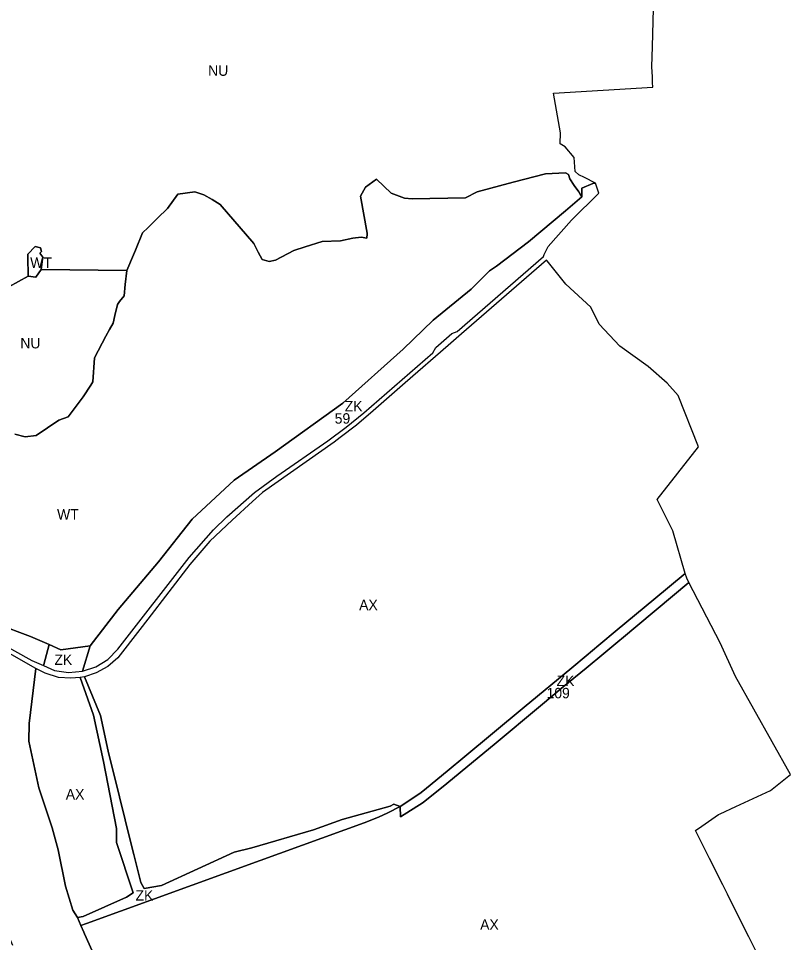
# Model space of a CAD drawing. Extents: x -521939 to -516426, y -1197857 to -1189551.
# Drawn here: x -518730 to -517990, y -1194658 to -1193772 of the extents above; entities that cross this region are included whole.
import ezdxf

# ---------------------------------------------------------------- set-up
doc = ezdxf.new("R2010")
doc.units = 0
for name, color, linetype in [('90640013', 7, 'Continuous'), ('90710013', 7, 'Continuous'), ('90710023', 7, 'Continuous'), ('90730013', 7, 'Continuous'), ('90760013', 7, 'Continuous'), ('ID_navrh', 7, 'Continuous')]:
    doc.layers.add(name, color=color, linetype=linetype)

msp = doc.modelspace()

# ---------------------------------------------------------------- linework, layer by layer
at = {"layer": '90640013'}
for points in [[(-518750.93, -1194352.24), (-518718.32, -1194364.43), (-518700.28, -1194372.27), (-518689.13, -1194377.12), (-518661.16, -1194373.51), (-518634.33, -1194338.71), (-518595.65, -1194293.01), (-518563.39, -1194252.1), (-518523.23, -1194214.71), (-518483.93, -1194187.46), (-518419.1, -1194140.67), (-518361.02, -1194088.99), (-518332.33, -1194061.21), (-518296.03, -1194031.57), (-518278.37, -1194013.9), (-518271.56, -1194009.45), (-518240.91, -1193986.11), (-518205.7, -1193956.46), (-518190.04, -1193942.98), (-518191.69, -1193940.25), (-518192.93, -1193938.18), (-518197.14, -1193931.95), (-518201.35, -1193925.72), (-518202.84, -1193921.41), (-518205.6, -1193919.97), (-518224.66, -1193920.83), (-518255.82, -1193928.83), (-518290.16, -1193938.05), (-518301.52, -1193943.97), (-518352.63, -1193944.77), (-518359.82, -1193944.27), (-518372.52, -1193939.49), (-518386.71, -1193925.92), (-518397.26, -1193933.79), (-518401.9, -1193942.24), (-518395.57, -1193977.74), (-518395.64, -1193978.34), (-518396.13, -1193982.66), (-518401.32, -1193981.65), (-518409.46, -1193982.4), (-518421.1, -1193985.13), (-518438.69, -1193985.6), (-518455.12, -1193990.99), (-518466.03, -1193994.3), (-518483.62, -1194003.52), (-518489.44, -1194004.93), (-518496.18, -1194003.01), (-518500.2, -1193996.02), (-518504.34, -1193987.83), (-518536.66, -1193950.17), (-518544.27, -1193945.64), (-518552.23, -1193940.9), (-518560.68, -1193938.11), (-518577.09, -1193940.5), (-518587.08, -1193954.16), (-518596.65, -1193963.46), (-518605.69, -1193972.18), (-518611, -1193977.3), (-518617.75, -1193994.01), (-518619.58, -1193998.55), (-518626.11, -1194013.41), (-518627.47, -1194026.91), (-518628.55, -1194037.69), (-518632.9, -1194043.41), (-518634.21, -1194045.19), (-518635, -1194046.24), (-518637.41, -1194056.78), (-518639.09, -1194064.19), (-518642.49, -1194070.13), (-518646.11, -1194076.43), (-518656.89, -1194097.14), (-518658.49, -1194120.34), (-518660.54, -1194123.45), (-518667.9, -1194134.61), (-518682.1, -1194153.73), (-518691.29, -1194156.96), (-518712.89, -1194171.66), (-518723.34, -1194172.97), (-518733.26, -1194170.62)], [(-518708.15, -1194012.57), (-518706.7, -1194002.7), (-518706.4, -1194000.63), (-518709.38, -1193996.94), (-518707.63, -1193995.36), (-518708.68, -1193991.67), (-518713.94, -1193990.62), (-518720.96, -1193997.82), (-518720.92, -1194000.53), (-518720.61, -1194019.07), (-518713.13, -1194019.83), (-518708.15, -1194012.57)]]:
    msp.add_lwpolyline(points, dxfattribs=at)
at = {"layer": '90710013'}
for points in [[(-518705.84, -1194392.3), (-518695.28, -1194396.89), (-518681.94, -1194398.95), (-518668.49, -1194397.81), (-518661.16, -1194373.51), (-518689.13, -1194377.12), (-518700.28, -1194372.27), (-518702.83, -1194381.83), (-518705.38, -1194391.38), (-518705.84, -1194392.3)], [(-518670.02, -1194641.47), (-518664.63, -1194639.51), (-518498.27, -1194579.14), (-518398.68, -1194543), (-518384.67, -1194537.56), (-518375.95, -1194533.52), (-518364.14, -1194527.29), (-518370.07, -1194525.28), (-518373.59, -1194527.14), (-518419.54, -1194539.87), (-518447.07, -1194549.8), (-518506.27, -1194566.99), (-518523.18, -1194571.3), (-518592.86, -1194603.17), (-518609.4, -1194606.14), (-518612.69, -1194600.31), (-518619.36, -1194573.41), (-518622.14, -1194562.23), (-518632.98, -1194518.19), (-518643.9, -1194474.45), (-518651.07, -1194440.25), (-518666.66, -1194403.24), (-518670.64, -1194403.6), (-518658.07, -1194439.91), (-518648.33, -1194484.39), (-518635.96, -1194548.55), (-518635.85, -1194562), (-518619.89, -1194610.13), (-518626.4, -1194614.29), (-518667.97, -1194632.81), (-518673.12, -1194633.99), (-518670.02, -1194641.47)]]:
    msp.add_lwpolyline(points, dxfattribs=at)
at = {"layer": '90710023'}
for points in [[(-518226.78, -1194000.03), (-518225.95, -1193998.27), (-518222.25, -1193990.41), (-518200, -1193965.24), (-518173.64, -1193939.33), (-518176.81, -1193929.72), (-518179.54, -1193930.3), (-518189.98, -1193934.67), (-518190.04, -1193942.98), (-518205.7, -1193956.46), (-518240.91, -1193986.11), (-518271.56, -1194009.45), (-518278.37, -1194013.9), (-518296.03, -1194031.57), (-518332.33, -1194061.21), (-518361.02, -1194088.99), (-518419.1, -1194140.67), (-518483.93, -1194187.46), (-518523.23, -1194214.71), (-518563.39, -1194252.1), (-518595.65, -1194293.01), (-518634.33, -1194338.71), (-518661.16, -1194373.51), (-518668.49, -1194397.81), (-518655.68, -1194393.54), (-518644.23, -1194386.38), (-518634.76, -1194376.7), (-518566.27, -1194288.86), (-518542.85, -1194262.27), (-518530.28, -1194249.78), (-518503.56, -1194226.5), (-518482.17, -1194210.72), (-518433.41, -1194176.9), (-518415.71, -1194163.89), (-518398.75, -1194149.91), (-518332.7, -1194092.34), (-518329.88, -1194087.32), (-518314.52, -1194073.94), (-518309.55, -1194072.16), (-518226.78, -1194000.03)], [(-518087.28, -1194312.72), (-518089.43, -1194308.57), (-518090.78, -1194303.93), (-518120.84, -1194329.01), (-518156.04, -1194358.17), (-518173.76, -1194372.91), (-518185.81, -1194382.9), (-518199.57, -1194394.33), (-518245.06, -1194432.12), (-518304.03, -1194481.14), (-518317.05, -1194491.98), (-518340.81, -1194511.5), (-518345.29, -1194514.98), (-518364.14, -1194527.29), (-518363.86, -1194537.39), (-518341.98, -1194523.73), (-518319.41, -1194505.51), (-518293.63, -1194484.18), (-518274.04, -1194467.87), (-518229.68, -1194431.04), (-518207.82, -1194412.86), (-518185.85, -1194394.67), (-518168.73, -1194380.59), (-518153.38, -1194367.87), (-518152.05, -1194366.76), (-518087.28, -1194312.72)]]:
    msp.add_lwpolyline(points, dxfattribs=at)
at = {"layer": '90730013'}
for points in [[(-518785.58, -1194054.84), (-518720.61, -1194019.07), (-518720.92, -1194000.53), (-518720.96, -1193997.82), (-518713.94, -1193990.62), (-518708.68, -1193991.67), (-518707.63, -1193995.36), (-518709.38, -1193996.94), (-518706.4, -1194000.63), (-518706.7, -1194002.7), (-518708.15, -1194012.57), (-518626.11, -1194013.41), (-518619.58, -1193998.55), (-518617.75, -1193994.01), (-518611, -1193977.3), (-518605.69, -1193972.18), (-518596.65, -1193963.46), (-518587.08, -1193954.16), (-518577.09, -1193940.5), (-518560.68, -1193938.11), (-518552.23, -1193940.9), (-518544.27, -1193945.64), (-518536.66, -1193950.17), (-518504.34, -1193987.83), (-518500.2, -1193996.02), (-518496.18, -1194003.01), (-518489.44, -1194004.93), (-518483.62, -1194003.52), (-518466.03, -1193994.3), (-518455.12, -1193990.99), (-518438.69, -1193985.6), (-518421.1, -1193985.13), (-518409.46, -1193982.4), (-518401.32, -1193981.65), (-518396.13, -1193982.66), (-518395.64, -1193978.34), (-518395.57, -1193977.74), (-518401.9, -1193942.24), (-518397.26, -1193933.79), (-518386.71, -1193925.92), (-518372.52, -1193939.49), (-518359.82, -1193944.27), (-518352.63, -1193944.77), (-518301.52, -1193943.97), (-518290.16, -1193938.05), (-518255.82, -1193928.83), (-518224.66, -1193920.83), (-518205.6, -1193919.97), (-518202.84, -1193921.41), (-518201.35, -1193925.72), (-518197.14, -1193931.95), (-518192.93, -1193938.18), (-518191.69, -1193940.25), (-518190.04, -1193942.98), (-518189.98, -1193934.67), (-518179.54, -1193930.3), (-518176.81, -1193929.72), (-518187.4, -1193924.36), (-518192.66, -1193921.7), (-518196.27, -1193918.65), (-518197.41, -1193905.18), (-518205.81, -1193894.97), (-518210.66, -1193892.12), (-518210.37, -1193881.64), (-518217.23, -1193843.45), (-518121.95, -1193837.64), (-518122.12, -1193833.28), (-518122.32, -1193828.03), (-518122.7, -1193818.24), (-518122.17, -1193798.73), (-518117.92, -1193642.32)], [(-518626.11, -1194013.41), (-518708.15, -1194012.57), (-518713.13, -1194019.83), (-518720.61, -1194019.07), (-518785.58, -1194054.84)], [(-518733.26, -1194170.62), (-518723.34, -1194172.97), (-518712.89, -1194171.66), (-518691.29, -1194156.96), (-518682.1, -1194153.73), (-518667.9, -1194134.61), (-518660.54, -1194123.45), (-518658.49, -1194120.34), (-518656.89, -1194097.14), (-518646.11, -1194076.43), (-518642.49, -1194070.13), (-518639.09, -1194064.19), (-518637.41, -1194056.78), (-518635, -1194046.24), (-518634.21, -1194045.19), (-518632.9, -1194043.41), (-518628.55, -1194037.69), (-518627.47, -1194026.91), (-518626.11, -1194013.41)], [(-518827.82, -1194325.64), (-518716.88, -1194387.49), (-518705.84, -1194392.3)], [(-518705.84, -1194392.3), (-518705.38, -1194391.38), (-518702.83, -1194381.83), (-518700.28, -1194372.27), (-518718.32, -1194364.43), (-518750.93, -1194352.24)], [(-518670.02, -1194641.47), (-518673.12, -1194633.99), (-518677.75, -1194626.77), (-518684.82, -1194603.84), (-518691.92, -1194568.93), (-518697.48, -1194547.94), (-518710.33, -1194509.64), (-518719.92, -1194464.77), (-518719.42, -1194447.81), (-518713.15, -1194395.12), (-518768.4, -1194363.91), (-518774.24, -1194362.95), (-518785.49, -1194356.68), (-518787.62, -1194357.85), (-518789.82, -1194390.1), (-518795.17, -1194469.16), (-518794.77, -1194500.94), (-518792.66, -1194516.7), (-518789.28, -1194532.25), (-518784.67, -1194547.47), (-518778.85, -1194562.27), (-518749.75, -1194628.33), (-518735.68, -1194660.28)], [(-518656.27, -1194672.17), (-518666.51, -1194649.62), (-518667.28, -1194647.83), (-518670.02, -1194641.47)]]:
    msp.add_lwpolyline(points, dxfattribs=at)
at = {"layer": '90760013'}
for points in [[(-518364.14, -1194527.29), (-518345.29, -1194514.98), (-518340.81, -1194511.5), (-518317.05, -1194491.98), (-518304.03, -1194481.14), (-518245.06, -1194432.12), (-518199.57, -1194394.33), (-518185.81, -1194382.9), (-518173.76, -1194372.91), (-518156.04, -1194358.17), (-518120.84, -1194329.01), (-518090.78, -1194303.93), (-518102.69, -1194263.13), (-518117.88, -1194232.97), (-518078.18, -1194182.6), (-518097.76, -1194133.37), (-518108.08, -1194121.7), (-518126.48, -1194105.44), (-518153.57, -1194086.04), (-518173.38, -1194065.05), (-518181.2, -1194048.7), (-518205.16, -1194026.8), (-518223.32, -1194004.32), (-518223.96, -1194003.53), (-518305.19, -1194074.33), (-518317.92, -1194085.37), (-518359.17, -1194121.38), (-518389.76, -1194148.03), (-518405.98, -1194161.92), (-518421.43, -1194173.75), (-518427.2, -1194178.07), (-518496.1, -1194226.49), (-518505.53, -1194235), (-518525.09, -1194252.86), (-518546.38, -1194272.96), (-518565.48, -1194295.54), (-518605.97, -1194347.8), (-518613.59, -1194357.67), (-518634.54, -1194384.93), (-518644.16, -1194393.22), (-518655.26, -1194399.4), (-518666.66, -1194403.24), (-518651.07, -1194440.25), (-518643.9, -1194474.45), (-518632.98, -1194518.19), (-518622.14, -1194562.23), (-518619.36, -1194573.41), (-518612.69, -1194600.31), (-518609.4, -1194606.14), (-518592.86, -1194603.17), (-518523.18, -1194571.3), (-518506.27, -1194566.99), (-518447.07, -1194549.8), (-518419.54, -1194539.87), (-518373.59, -1194527.14), (-518370.07, -1194525.28), (-518364.14, -1194527.29)], [(-518087.28, -1194312.72), (-518152.05, -1194366.76), (-518153.38, -1194367.87), (-518168.73, -1194380.59), (-518185.85, -1194394.67), (-518207.82, -1194412.86), (-518229.68, -1194431.04), (-518274.04, -1194467.87), (-518293.63, -1194484.18), (-518319.41, -1194505.51), (-518341.98, -1194523.73), (-518363.86, -1194537.39), (-518364.14, -1194527.29), (-518375.95, -1194533.52), (-518384.67, -1194537.56), (-518398.68, -1194543), (-518498.27, -1194579.14), (-518664.63, -1194639.51), (-518670.02, -1194641.47), (-518667.28, -1194647.83), (-518666.51, -1194649.62), (-518656.27, -1194672.17)], [(-518018.4, -1194675.4), (-518029.91, -1194652.44), (-518045.86, -1194620.61), (-518050.45, -1194611.46), (-518054.9, -1194602.59), (-518067.64, -1194577.17), (-518070.73, -1194570.99), (-518081.12, -1194550.28), (-518075.09, -1194546.2), (-518058.86, -1194535.22), (-518057.31, -1194534.5), (-518042.23, -1194527.44), (-518009.18, -1194511.97), (-517989.96, -1194496.69), (-518042.83, -1194402.69), (-518057.45, -1194370.47), (-518087.28, -1194312.72)], [(-518673.12, -1194633.99), (-518667.97, -1194632.81), (-518626.4, -1194614.29), (-518619.89, -1194610.13), (-518635.85, -1194562), (-518635.96, -1194548.55), (-518648.33, -1194484.39), (-518658.07, -1194439.91), (-518670.64, -1194403.6), (-518679.67, -1194404.43), (-518691.62, -1194403.86), (-518704.16, -1194399.65), (-518713.15, -1194395.12), (-518719.42, -1194447.81), (-518719.92, -1194464.77), (-518710.33, -1194509.64), (-518697.48, -1194547.94), (-518691.92, -1194568.93), (-518684.82, -1194603.84), (-518677.75, -1194626.77), (-518673.12, -1194633.99)]]:
    msp.add_lwpolyline(points, dxfattribs=at)

# ---------------------------------------------------------------- texts
at = {"layer": '90640013'}
for rotation, p in [(360, (-518718.61, -1194011.03)), (0, (-518692.84, -1194252.33))]:
    msp.add_text('WT', height=10, rotation=rotation, dxfattribs=at).set_placement(p)
at = {"layer": '90710013'}
for rotation, p in [(0, (-518695.39, -1194391.72)), (360, (-518617.65, -1194617.67))]:
    msp.add_text('ZK', height=10, rotation=rotation, dxfattribs=at).set_placement(p)
at = {"layer": '90710023'}
for p in [(-518417.15, -1194148.59), (-518214.13, -1194411.9)]:
    msp.add_text('ZK', height=10, rotation=360, dxfattribs=at).set_placement(p)
at = {"layer": '90730013'}
for p in [(-518548.11, -1193826.91), (-518728.03, -1194088.23)]:
    msp.add_text('NU', height=10, rotation=0, dxfattribs=at).set_placement(p)
at = {"layer": '90760013'}
for p in [(-518403.35, -1194339.22), (-518684.48, -1194520.75), (-518287.4, -1194645.6)]:
    msp.add_text('AX', height=10, rotation=0, dxfattribs=at).set_placement(p)
at = {"layer": 'ID_navrh'}
for s, p in [('59', (-518426.79, -1194160.38)), ('109', (-518223.77, -1194423.69))]:
    msp.add_text(s, height=10, rotation=360, dxfattribs=at).set_placement(p)

doc.saveas('drawing.dxf')
